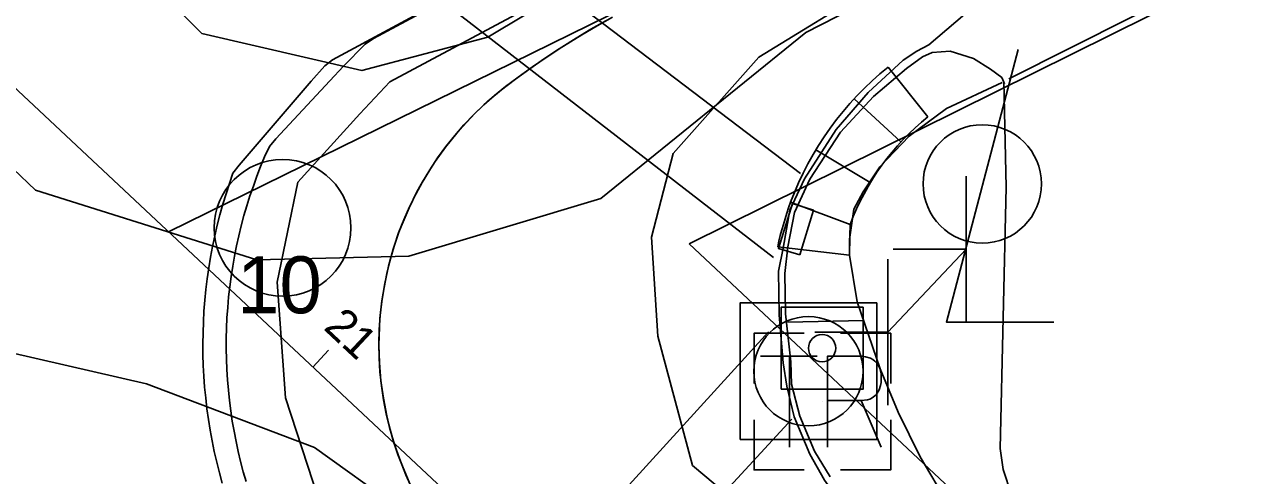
# Model space of a CAD drawing. Extents: x 1475900 to 1484331, y 375914 to 383395.
# Drawn here: x 1479629.9 to 1479735.5, y 379897.7 to 379936.7 of the extents above; entities that cross this region are included whole.
import ezdxf

# ---------------------------------------------------------------- set-up
doc = ezdxf.new("R2010")
doc.units = 0
for name, color, linetype in [('Default', 7, 'Continuous'), ('LT_X_Poles', 7, 'Continuous'), ('PM_X_Crosswalk', 7, 'Continuous'), ('PM_X_Misc', 7, 'Continuous'), ('PV_X_Curb', 7, 'Continuous'), ('PV_X_Walk', 7, 'Continuous'), ('RW_X_CL_20', 7, 'Continuous'), ('RW_X_Esmt_SH', 7, 'Continuous'), ('RW_X_Text', 7, 'Continuous'), ('SG_X_Poles', 7, 'Continuous'), ('SG_X_PullBox', 7, 'Continuous'), ('SG_X_PullBox (Construction)', 7, 'Continuous'), ('SN_X_Public', 7, 'Continuous')]:
    doc.layers.add(name, color=color, linetype=linetype)

# ---------------------------------------------------------------- blocks, each defined once
blk = doc.blocks.new('SPOLE')
at = {"layer": 'SG_X_Poles'}
blk.add_lwpolyline([(-0.01905, -0.01905), (0.01905, -0.01905), (0.01905, 0.01905), (-0.01905, 0.01905)], close=True, dxfattribs=at)
blk.add_circle((0, 0), 0.01524, dxfattribs=at)
blk = doc.blocks.new('POINT_DISPLAY')
at = {"layer": 'Default'}
blk.add_line((0, 0), (0, 0), dxfattribs=at)
blk = doc.blocks.new('SIGPB')
at = {"layer": 'SG_X_PullBox'}
for p, q in [((-0.01722, 0.0127), (-0.00142, 0.0127)), ((-0.00922, 0.0127), (-0.00922, -0.0127)), ((0.01082, 0.0003), (0.01642, -0.0127))]:
    blk.add_line(p, q, dxfattribs=at)
for points in [[(-0.00508, 0.01905), (-0.01905, 0.01905), (-0.01905, 0.00508)], [(0.01905, 0.00508), (0.01905, 0.01905), (0.00508, 0.01905)], [(0.00142, -0.0127), (0.00142, 0.0127), (0.01102, 0.0127), (0.01202, 0.0125), (0.01342, 0.0121), (0.01402, 0.0117), (0.01462, 0.0113), (0.01542, 0.0103), (0.01602, 0.0093), (0.01642, 0.0077), (0.01642, 0.0053), (0.01622, 0.0045), (0.01582, 0.0033), (0.01502, 0.0019), (0.01422, 0.0013), (0.01362, 0.0009), (0.01322, 0.0007), (0.01262, 0.0005), (0.01082, 0.0003), (0.00142, 0.0003)], [(-0.01905, -0.00508), (-0.01905, -0.01905), (-0.00508, -0.01905)], [(0.00508, -0.01905), (0.01905, -0.01905), (0.01905, -0.00508)]]:
    blk.add_lwpolyline(points, dxfattribs=at)
at = {"layer": 'SG_X_PullBox (Construction)'}
blk.add_blockref('POINT_DISPLAY', (0, 0), dxfattribs=at)
blk = doc.blocks.new('SGN1P')
at = {"layer": 'SN_X_Public'}
for p, q in [((0, 0.02032), (0, -0.02032)), ((0, 0), (-0.02032, 0))]:
    blk.add_line(p, q, dxfattribs=at)
blk = doc.blocks.new('LPOLE')
at = {"layer": 'LT_X_Poles'}
blk.add_lwpolyline([(0.00999, 0.03751), (-0.01001, -0.0385), (0.02, -0.0385)], dxfattribs=at)
blk.add_circle((0, 0), 0.01651, dxfattribs=at)
blk = doc.blocks.new('SPED')
at = {"layer": 'SG_X_Poles'}
blk.add_lwpolyline([(-0.01143, -0.01143), (0.01143, -0.01143), (0.01143, 0.01143), (-0.01143, 0.01143)], close=True, dxfattribs=at)
blk.add_circle((0, 0), 0.00381, dxfattribs=at)

msp = doc.modelspace()

# ---------------------------------------------------------------- linework, layer by layer
at = {"layer": 'Default'}
msp.add_line((1479704.52, 379910.06), (1479711.29, 379917.24), dxfattribs=at)
at = {"layer": 'PM_X_Crosswalk'}
for p, q in [((1479696.98, 379923.76), (1479671.85, 379942.85)), ((1479663.29, 379940.79), (1479694.65, 379916.51)), ((1479656.67, 379868.95), (1479694.22, 379910.08)), ((1479661.06, 379864.45), (1479696.23, 379902.55))]:
    msp.add_line(p, q, dxfattribs=at)
at = {"layer": 'PM_X_Misc'}
for points in [[(1479649.05, 379897.14), (1479648.8, 379898), (1479648.57, 379898.87), (1479648.37, 379899.74), (1479648.18, 379900.62), (1479648.01, 379901.5), (1479647.85, 379902.38), (1479647.72, 379903.27), (1479647.61, 379904.15), (1479647.51, 379905.04), (1479647.44, 379905.94), (1479647.38, 379906.83), (1479647.35, 379907.73), (1479647.33, 379908.62), (1479647.33, 379909.52), (1479647.35, 379910.41), (1479647.39, 379911.31), (1479647.45, 379912.2), (1479647.53, 379913.1), (1479647.63, 379913.99), (1479647.75, 379914.87), (1479647.89, 379915.76), (1479648.04, 379916.64), (1479648.22, 379917.52), (1479648.41, 379918.39), (1479648.63, 379919.26), (1479648.86, 379920.13), (1479649.11, 379920.99), (1479649.38, 379921.84), (1479649.67, 379922.69), (1479649.97, 379923.54), (1479650.3, 379924.37), (1479650.64, 379925.2), (1479651.06, 379926.11), (1479651.62, 379926.77), (1479656.27, 379931.79), (1479657.46, 379933.04), (1479659.33, 379934.94), (1479660.06, 379935.45), (1479679.63, 379945.95)], [(1479646.98, 379897), (1479646.73, 379897.91), (1479646.5, 379898.82), (1479646.29, 379899.74), (1479646.1, 379900.66), (1479645.94, 379901.58), (1479645.79, 379902.51), (1479645.66, 379903.44), (1479645.55, 379904.37), (1479645.46, 379905.31), (1479645.39, 379906.25), (1479645.34, 379907.18), (1479645.31, 379908.12), (1479645.3, 379909.06), (1479645.32, 379910), (1479645.35, 379910.94), (1479645.4, 379911.88), (1479645.48, 379912.82), (1479645.57, 379913.75), (1479645.68, 379914.68), (1479645.82, 379915.61), (1479645.97, 379916.54), (1479646.14, 379917.46), (1479646.34, 379918.38), (1479646.55, 379919.3), (1479646.78, 379920.21), (1479647.04, 379921.11), (1479647.31, 379922.01), (1479647.6, 379922.91), (1479647.91, 379923.79), (1479648.45, 379924.48), (1479654.67, 379931.76), (1479655.84, 379933.09), (1479656.52, 379933.59), (1479672.44, 379942.2)], [(1479680.73, 379937.28), (1479679.39, 379936.53), (1479678.06, 379935.76), (1479676.1, 379934.55), (1479674.83, 379933.7), (1479673.57, 379932.83), (1479672.33, 379931.93), (1479671.12, 379931.01), (1479669.93, 379930.01), (1479668.83, 379928.97), (1479667.78, 379927.84), (1479667.26, 379927.27), (1479666.29, 379926.06), (1479665.4, 379924.81), (1479664.98, 379924.18), (1479664.18, 379922.86), (1479663.81, 379922.19), (1479663.13, 379920.8), (1479662.53, 379919.39), (1479662.25, 379918.69), (1479661.77, 379917.23), (1479661.36, 379915.77), (1479661.04, 379914.27), (1479660.79, 379912.77), (1479660.62, 379911.24), (1479660.57, 379910.48), (1479660.53, 379908.93), (1479660.57, 379907.4), (1479660.7, 379905.86), (1479660.91, 379904.35), (1479661.2, 379902.83), (1479661.38, 379902.09), (1479661.8, 379900.59), (1479662.3, 379899.15), (1479662.85, 379897.74), (1479663.49, 379896.33)], [(1479680.14, 379936.96), (1479678.86, 379936.24), (1479677.59, 379935.48), (1479676.33, 379934.69), (1479675.07, 379933.86), (1479673.81, 379933), (1479672.56, 379932.11), (1479671.47, 379931.29), (1479670.52, 379930.52), (1479669.6, 379929.71), (1479668.73, 379928.87), (1479667.88, 379927.98), (1479667.08, 379927.06), (1479666.32, 379926.11), (1479665.6, 379925.12), (1479664.93, 379924.1), (1479664.29, 379923.06), (1479663.71, 379921.99), (1479663.17, 379920.89), (1479662.68, 379919.77), (1479662.23, 379918.63), (1479661.84, 379917.48), (1479661.5, 379916.31), (1479661.21, 379915.12), (1479660.97, 379913.92), (1479660.78, 379912.72), (1479660.64, 379911.5), (1479660.56, 379910.28), (1479660.53, 379909.06), (1479660.55, 379907.84), (1479660.62, 379906.62), (1479660.75, 379905.41), (1479660.93, 379904.2), (1479661.16, 379903), (1479661.45, 379901.81), (1479661.78, 379900.64), (1479662.17, 379899.48), (1479662.61, 379898.32), (1479663.13, 379897.09)]]:
    msp.add_lwpolyline(points, dxfattribs=at)
msp.add_circle((1479652.2, 379919.08), 5.91, dxfattribs=at)
at = {"layer": 'PV_X_Curb'}
for p, q in [((1479696.12, 379921.28), (1479701.28, 379919.37)), ((1479701.22, 379916.7), (1479695.01, 379917.43))]:
    msp.add_line(p, q, dxfattribs=at)
for points in [[(1479735.87, 379861.85), (1479733.79, 379863.76), (1479718.7, 379877.9), (1479705.48, 379890.33), (1479700.95, 379894.58), (1479699.05, 379897.26), (1479697.78, 379899.5), (1479696.44, 379902.73), (1479695.78, 379905.4), (1479695.47, 379907.42), (1479695.14, 379911.53), (1479695.08, 379915.32), (1479695.47, 379917.32), (1479696.05, 379920.61), (1479697.32, 379923.3), (1479700.06, 379927.56), (1479702.83, 379930.77), (1479705.86, 379933.57), (1479707.03, 379934.35), (1479708.06, 379934.88), (1479711.18, 379937.55)], [(1479699.53, 379897.55), (1479698.18, 379899.76), (1479696.91, 379902.81), (1479696.19, 379905.55), (1479696.15, 379907.48), (1479695.69, 379911.64), (1479695.62, 379915.12), (1479695.89, 379917.42), (1479696.46, 379920.4), (1479697.79, 379923.29), (1479700.42, 379927.33), (1479703.29, 379930.44), (1479706.13, 379932.85), (1479707.53, 379933.86), (1479708.37, 379934.22), (1479709.93, 379934.33), (1479711.93, 379933.72), (1479713.41, 379932.79), (1479714.37, 379932.06), (1479714.61, 379931.51)], [(1479714.57, 379931.72), (1479714.77, 379922.6), (1479714.23, 379900.01), (1479714.49, 379898.19), (1479715.22, 379896), (1479717.04, 379893.8), (1479731.94, 379880.01), (1479745.71, 379867.31), (1479763.19, 379850.75), (1479775.06, 379839.58), (1479781.93, 379833.12), (1479783.78, 379830.71), (1479784.21, 379828.71), (1479783.14, 379825.91)]]:
    msp.add_lwpolyline(points, dxfattribs=at)
msp.add_lwpolyline([(1479696.91, 379916.73), (1479695.07, 379917.3), (1479696.27, 379921.17), (1479698.11, 379920.6)], close=True, dxfattribs=at)
for centre, radius, start, end in [((1479721.49, 379911.87), 27.06, 159.644, 168.1453), ((1479741.91, 379917.08), 40.7, 176.7768, 180.5391)]:
    msp.add_arc(centre, radius, start, end, dxfattribs=at)
at = {"layer": 'PV_X_Walk'}
for p, q in [((1479704.55, 379932.97), (1479707.99, 379928.68)), ((1479701.62, 379930.23), (1479705.66, 379926.5)), ((1479698.3, 379925.81), (1479703.01, 379922.98)), ((1479695.88, 379910.93), (1479702.42, 379911.07))]:
    msp.add_line(p, q, dxfattribs=at)
for points in [[(1479764.35, 379957.04), (1479747.94, 379948.68), (1479730.88, 379939.97), (1479715, 379931.95)], [(1479714.41, 379931.65), (1479709.59, 379929.39), (1479706.36, 379927.01), (1479703.83, 379924.36), (1479702.38, 379922.18), (1479701.6, 379920.68), (1479701.23, 379918.28), (1479701.22, 379916.7), (1479701.87, 379912.68), (1479703.86, 379906.89), (1479705.42, 379903.15), (1479707.31, 379899.27), (1479709.71, 379895.26), (1479713.76, 379890.53), (1479726.08, 379878.96), (1479737.97, 379867.99), (1479746.24, 379860.49), (1479749.39, 379863.57), (1479751.94, 379861.3), (1479749.04, 379858.04), (1479762.48, 379845.22), (1479775.26, 379833.23), (1479781.25, 379827.72), (1479783.04, 379825.88)]]:
    msp.add_lwpolyline(points, dxfattribs=at)
for radius in [27.06, 21.56]:
    msp.add_arc((1479721.49, 379911.87), radius, 128.7654, 159.644, dxfattribs=at)
at = {"layer": 'RW_X_CL_20'}
for p, q in [((1479642.33, 379918.73), (1479870.13, 380030.67)), ((1479654.81, 379907.04), (1479656.18, 379908.5))]:
    msp.add_line(p, q, dxfattribs=at)
msp.add_lwpolyline([(1477185.15, 382318.79), (1478151.68, 381373.49), (1479566.7, 379989.54), (1480555.97, 379063.33), (1481343.87, 378335.5), (1481853.32, 377853.22), (1482587.9, 377143.51), (1482849.67, 376882.07), (1483668.91, 376080.34), (1483878.1, 376026.7), (1484025.82, 375988.83), (1484313.71, 375915.02)], dxfattribs=at)
at = {"layer": 'RW_X_Esmt_SH'}
for q in [(1479879.01, 380012.75), (1479967.32, 379655.56)]:
    msp.add_line((1479687.35, 379917.68), q, dxfattribs=at)
at = {"layer": 'RW_X_Text'}
for points in [[(1479498.76, 380054.27), (1479542.61, 380009.77), (1479579.04, 379974.72), (1479593.11, 379960.7), (1479603.72, 379949.15), (1479613.43, 379938.94), (1479630.83, 379922.33), (1479649.98, 379916.32), (1479663.12, 379916.63), (1479679.72, 379921.61), (1479697.44, 379935.96), (1479749.58, 379962.61), (1479797.99, 379987.23)], [(1479792.31, 379997.56), (1479710.02, 379956.74), (1479682.58, 379943.12), (1479669.95, 379935.54), (1479659.06, 379932.66), (1479645.23, 379935.86), (1479631.96, 379949.18), (1479613.32, 379970.31), (1479554.76, 380028.14)], [(1479792.31, 379997.56), (1479688.12, 379945.87), (1479680.71, 379942), (1479661.48, 379931.68), (1479658.87, 379928.92), (1479653.52, 379923.03), (1479651.72, 379914.38), (1479652.44, 379904.37), (1479656.24, 379892.75), (1479663.84, 379880.53), (1479675, 379870.68), (1479716.91, 379832.05), (1479737.94, 379812.66)], [(1479797.55, 379798.42), (1479779.29, 379815.04), (1479755.95, 379837.17), (1479710.6, 379878.47), (1479700.46, 379887.97), (1479695.14, 379892.26), (1479687.63, 379898.54), (1479684.65, 379909.71), (1479684.09, 379918.26), (1479685.98, 379925.49), (1479693.36, 379933.84), (1479703.54, 379940.07), (1479719.59, 379947.28), (1479755.69, 379965.71), (1479770.46, 379973.23)], [(1479733.47, 379829.75), (1479698.71, 379860.92), (1479681.21, 379878.12), (1479669.41, 379889.71), (1479654.95, 379900.1), (1479640.42, 379905.58), (1479623.99, 379909.38), (1479606.71, 379909.37), (1479595.29, 379905.22), (1479570.47, 379896.19), (1479545.09, 379885.58), (1479522.33, 379874.3), (1479499.6, 379861.91)]]:
    msp.add_lwpolyline(points, dxfattribs=at)

# ---------------------------------------------------------------- block references
at = {"layer": 'LT_X_Poles', "xscale": 310.00000000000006, "yscale": 310.00000000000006}
msp.add_blockref('LPOLE', (1479712.69, 379922.87), dxfattribs=at)
at = {"layer": 'SG_X_Poles', "xscale": 310.00000000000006, "yscale": 310.00000000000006}
for name, p in [('SPOLE', (1479697.66, 379906.68)), ('SPED', (1479698.84, 379908.67))]:
    msp.add_blockref(name, p, dxfattribs=at)
at = {"layer": 'SG_X_PullBox', "xscale": 310.00000000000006, "yscale": 310.00000000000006}
msp.add_blockref('SIGPB', (1479698.87, 379904.06), dxfattribs=at)
at = {"layer": 'SN_X_Public', "xscale": 310.00000000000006, "yscale": 310.00000000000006}
for p in [(1479711.29, 379917.24), (1479704.52, 379910.06)]:
    msp.add_blockref('SGN1P', p, dxfattribs=at)

# ---------------------------------------------------------------- texts
at = {"layer": 'PM_X_Misc'}
msp.add_text('10', height=4.921, dxfattribs=at).set_placement((1479648.27, 379911.69))
at = {"layer": 'RW_X_CL_20'}
msp.add_text('21', height=2.8, rotation=316.8859, dxfattribs=at).set_placement((1479655.65, 379910.37))

doc.saveas('drawing.dxf')
